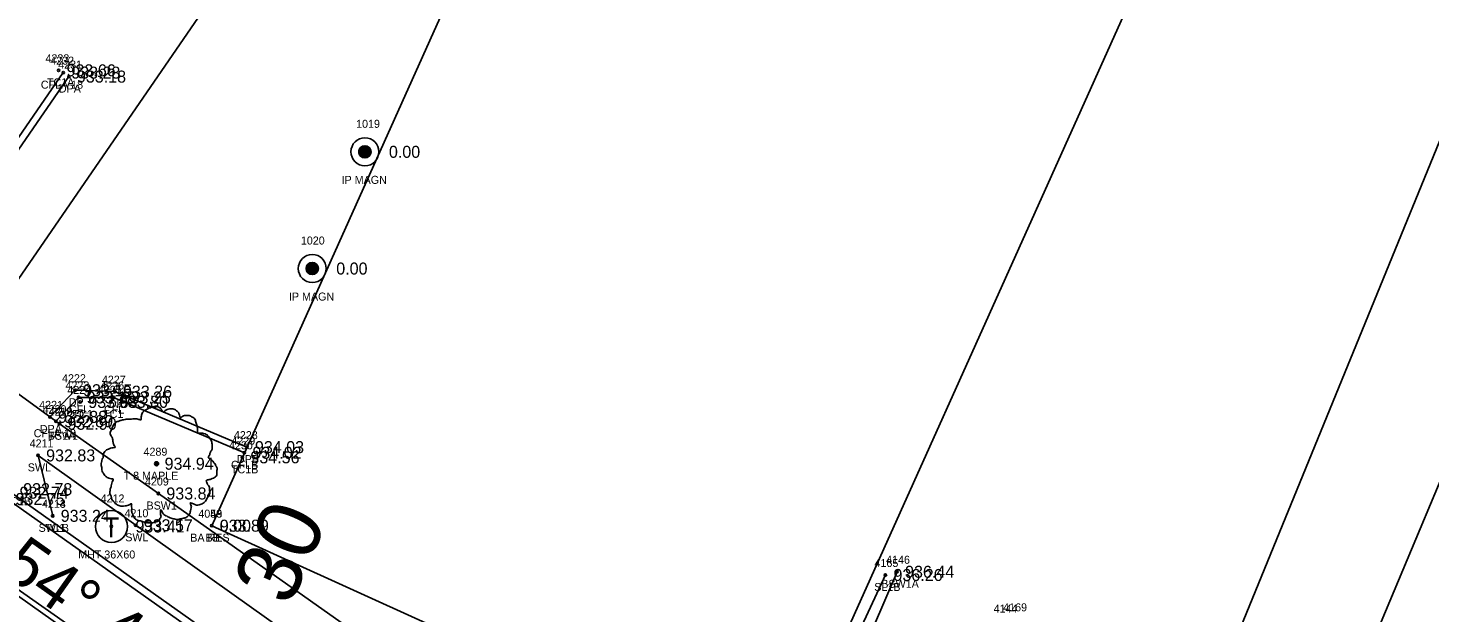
# Model space of a CAD drawing. Extents: x 1575382 to 1578175, y 1099175 to 1101955.
# Drawn here: x 1577218.2 to 1577393.3, y 1101400.1 to 1101473.2 of the extents above; entities that cross this region are included whole.
import ezdxf

# ---------------------------------------------------------------- set-up
doc = ezdxf.new("R2010")
doc.units = 0
for name, color, linetype in [('RD_EX_Bldg', 7, 'Continuous'), ('RD_EX_Bldg_txCode', 7, 'Continuous'), ('RD_EX_Conc', 7, 'Continuous'), ('RD_EX_Conc_txCode', 7, 'Continuous'), ('RD_EX_DR_Pipe', 7, 'Continuous'), ('RD_EX_Driveway', 7, 'Continuous'), ('RD_EX_Driveway_txCode', 7, 'Continuous'), ('RD_EX_DV_Prop_txCode', 7, 'Continuous'), ('RD_EX_DV_PropPin', 7, 'Continuous'), ('RD_EX_Road', 7, 'Continuous'), ('RD_EX_SU_Telecom', 7, 'Continuous'), ('RD_EX_TX_Bldg_ELEV', 7, 'Continuous'), ('RD_EX_TX_Conc_ELEV', 7, 'Continuous'), ('RD_EX_TX_Driveway_ELEV', 7, 'Continuous'), ('RD_EX_TX_DV_Prop_ELEV', 7, 'Continuous'), ('RD_EX_TX_Road_ELEV', 7, 'Continuous'), ('RD_EX_TX_UT_ELEV', 7, 'Continuous'), ('RD_EX_TX_VEG_ELEV', 7, 'Continuous'), ('RD_EX_UT', 7, 'Continuous'), ('RD_EX_UT_txCode', 7, 'Continuous'), ('RD_EX_VEG', 7, 'Continuous'), ('RD_EX_VEG_txCode', 7, 'Continuous'), ('RD_HC_Cl', 7, 'Continuous'), ('RD_HC_Data', 7, 'Continuous'), ('RD_HC_TX_Sta50', 7, 'Continuous'), ('RD_SMD_Locator', 7, 'Continuous')]:
    doc.layers.add(name, color=color, linetype=linetype)

msp = doc.modelspace()

# ---------------------------------------------------------------- linework, layer by layer
at = {"layer": 'RD_EX_Bldg'}
msp.add_lwpolyline([(1577241.11, 1101410.99), (1577311.94, 1101378.81), (1577394.95, 1101563.59), (1577324.12, 1101595.78), (1577241.11, 1101410.99)], dxfattribs=at)
at = {"layer": 'RD_EX_Conc'}
for points in [[(1577326.74, 1101405.23), (1577316.35, 1101381.05), (1577314.7, 1101377.45), (1577312.77, 1101373.03), (1577307.57, 1101368.22), (1577302.65, 1101367.84), (1577295.88, 1101371.65), (1577262.96, 1101394.89), (1577234.44, 1101415.01), (1577222.09, 1101423.72), (1577202.94, 1101437.61), (1577200.92, 1101438.92), (1577194.11, 1101443.95), (1577177.58, 1101455.53), (1577173.58, 1101458.39), (1577156.82, 1101470.2), (1577152.82, 1101472.9), (1577143.37, 1101479.79), (1577139.03, 1101482.93)], [(1577222.56, 1101467.58), (1577206.78, 1101444.68), (1577203.8, 1101441.89)], [(1577221.65, 1101424.04), (1577224.47, 1101427.01), (1577228.85, 1101427), (1577245.2, 1101420.1)], [(1577305.91, 1101358.4), (1577259.94, 1101390.92), (1577231.61, 1101411.04), (1577219.42, 1101419.77), (1577221.24, 1101412.22)], [(1577306.23, 1101358.15), (1577304.05, 1101352.9), (1577257.21, 1101385.98), (1577216.1, 1101415.11)]]:
    msp.add_lwpolyline(points, dxfattribs=at)
at = {"layer": 'RD_EX_DR_Pipe'}
msp.add_lwpolyline([(1577244.79, 1101065.98), (1577363.73, 1101342.96), (1577363.73, 1101342.96), (1577441.43, 1101528.3)], dxfattribs=at)
at = {"layer": 'RD_EX_Driveway'}
for points in [[(1577223.27, 1101467.09), (1577203.54, 1101438.52), (1577202.94, 1101437.61)], [(1577220.9, 1101424.58), (1577224.04, 1101427.91), (1577229.02, 1101427.73), (1577245.51, 1101420.8)]]:
    msp.add_lwpolyline(points, dxfattribs=at)
at = {"layer": 'RD_EX_DV_PropPin'}
for p, q in [((1577259.55, 1101457.4), (1577259.55, 1101457.99)), ((1577259.58, 1101457.33), (1577259.58, 1101458.06)), ((1577259.62, 1101457.27), (1577259.62, 1101458.12)), ((1577259.65, 1101457.22), (1577259.65, 1101458.17)), ((1577259.69, 1101457.18), (1577259.69, 1101458.21)), ((1577259.72, 1101457.14), (1577259.72, 1101458.25)), ((1577259.76, 1101457.11), (1577259.76, 1101458.28)), ((1577259.79, 1101457.08), (1577259.79, 1101458.3)), ((1577259.83, 1101457.06), (1577259.83, 1101458.33)), ((1577259.86, 1101457.04), (1577259.86, 1101458.35)), ((1577259.9, 1101457.02), (1577259.9, 1101458.37)), ((1577259.93, 1101457), (1577259.93, 1101458.39)), ((1577259.97, 1101456.99), (1577259.97, 1101458.4)), ((1577260, 1101456.97), (1577260, 1101458.42)), ((1577260.04, 1101456.96), (1577260.04, 1101458.43)), ((1577260.07, 1101456.95), (1577260.07, 1101458.44)), ((1577260.11, 1101456.95), (1577260.11, 1101458.44)), ((1577260.14, 1101456.94), (1577260.14, 1101458.45)), ((1577260.18, 1101456.94), (1577260.18, 1101458.45)), ((1577260.21, 1101456.93), (1577260.21, 1101458.46)), ((1577260.25, 1101456.93), (1577260.25, 1101458.46)), ((1577260.28, 1101456.93), (1577260.28, 1101458.46)), ((1577260.32, 1101456.94), (1577260.32, 1101458.45)), ((1577260.35, 1101456.94), (1577260.35, 1101458.45)), ((1577260.39, 1101456.95), (1577260.39, 1101458.44)), ((1577260.42, 1101456.95), (1577260.42, 1101458.44)), ((1577260.46, 1101456.96), (1577260.46, 1101458.43)), ((1577260.49, 1101456.97), (1577260.49, 1101458.42)), ((1577260.53, 1101456.99), (1577260.53, 1101458.4)), ((1577260.56, 1101457), (1577260.56, 1101458.39)), ((1577260.6, 1101457.02), (1577260.6, 1101458.37)), ((1577260.63, 1101457.04), (1577260.63, 1101458.35)), ((1577260.67, 1101457.06), (1577260.67, 1101458.33)), ((1577260.7, 1101457.08), (1577260.7, 1101458.3)), ((1577260.74, 1101457.11), (1577260.74, 1101458.28)), ((1577260.77, 1101457.14), (1577260.77, 1101458.25)), ((1577260.81, 1101457.18), (1577260.81, 1101458.21)), ((1577260.85, 1101457.22), (1577260.85, 1101458.17)), ((1577260.88, 1101457.27), (1577260.88, 1101458.12)), ((1577260.92, 1101457.33), (1577260.92, 1101458.06)), ((1577260.95, 1101457.4), (1577260.95, 1101457.99)), ((1577259.51, 1101457.5), (1577259.51, 1101457.89)), ((1577260.99, 1101457.5), (1577260.99, 1101457.89)), ((1577252.94, 1101442.91), (1577252.94, 1101443.31)), ((1577252.97, 1101442.81), (1577252.97, 1101443.41)), ((1577253.01, 1101442.74), (1577253.01, 1101443.48)), ((1577253.04, 1101442.68), (1577253.04, 1101443.54)), ((1577253.08, 1101442.64), (1577253.08, 1101443.58)), ((1577253.11, 1101442.59), (1577253.11, 1101443.62)), ((1577253.15, 1101442.56), (1577253.15, 1101443.66)), ((1577253.18, 1101442.53), (1577253.18, 1101443.69)), ((1577253.22, 1101442.5), (1577253.22, 1101443.72)), ((1577253.25, 1101442.47), (1577253.25, 1101443.74)), ((1577253.29, 1101442.45), (1577253.29, 1101443.77)), ((1577253.32, 1101442.43), (1577253.32, 1101443.79)), ((1577253.36, 1101442.42), (1577253.36, 1101443.8)), ((1577253.39, 1101442.4), (1577253.39, 1101443.82)), ((1577253.43, 1101442.39), (1577253.43, 1101443.83)), ((1577253.46, 1101442.38), (1577253.46, 1101443.84)), ((1577253.5, 1101442.37), (1577253.5, 1101443.85)), ((1577253.53, 1101442.36), (1577253.53, 1101443.86)), ((1577253.57, 1101442.36), (1577253.57, 1101443.86)), ((1577253.6, 1101442.35), (1577253.6, 1101443.87)), ((1577253.64, 1101442.35), (1577253.64, 1101443.87)), ((1577253.67, 1101442.35), (1577253.67, 1101443.87)), ((1577253.71, 1101442.35), (1577253.71, 1101443.87)), ((1577253.74, 1101442.35), (1577253.74, 1101443.87)), ((1577253.78, 1101442.36), (1577253.78, 1101443.86)), ((1577253.81, 1101442.36), (1577253.81, 1101443.86)), ((1577253.85, 1101442.37), (1577253.85, 1101443.85)), ((1577253.88, 1101442.38), (1577253.88, 1101443.84)), ((1577253.92, 1101442.39), (1577253.92, 1101443.83)), ((1577253.95, 1101442.4), (1577253.95, 1101443.82)), ((1577253.99, 1101442.42), (1577253.99, 1101443.8)), ((1577254.02, 1101442.43), (1577254.02, 1101443.79)), ((1577254.06, 1101442.45), (1577254.06, 1101443.77)), ((1577254.09, 1101442.47), (1577254.09, 1101443.74)), ((1577254.13, 1101442.5), (1577254.13, 1101443.72)), ((1577254.16, 1101442.53), (1577254.16, 1101443.69)), ((1577254.2, 1101442.56), (1577254.2, 1101443.66)), ((1577254.23, 1101442.59), (1577254.23, 1101443.62)), ((1577254.27, 1101442.64), (1577254.27, 1101443.58)), ((1577254.3, 1101442.68), (1577254.3, 1101443.54)), ((1577254.34, 1101442.74), (1577254.34, 1101443.48)), ((1577254.37, 1101442.81), (1577254.37, 1101443.41)), ((1577254.41, 1101442.91), (1577254.41, 1101443.31))]:
    msp.add_line(p, q, dxfattribs=at)
for centre, radius in [((1577260.25, 1101457.69), 1.75), ((1577260.25, 1101457.69), 0.761), ((1577253.67, 1101443.11), 1.75), ((1577253.67, 1101443.11), 0.761)]:
    msp.add_circle(centre, radius, dxfattribs=at)
at = {"layer": 'RD_EX_Road'}
msp.add_lwpolyline([(1577350.99, 1101394.65), (1577333.62, 1101354.38), (1577330.31, 1101348.32), (1577323.84, 1101345.4), (1577317.43, 1101344.5), (1577311.61, 1101346.41), (1577303.25, 1101352.4), (1577256.62, 1101385.27), (1577215.6, 1101414.32), (1577175.52, 1101442.94), (1577135.2, 1101471.71)], dxfattribs=at)
at = {"layer": 'RD_EX_SU_Telecom'}
msp.add_circle((1577228.58, 1101410.89), 2, dxfattribs=at)
at = {"layer": 'RD_EX_UT'}
msp.add_line((1577284.56, 1101540.07), (1577198.95, 1101415.64), dxfattribs=at)
for points in [[(1577437.16, 1101563.25), (1577337.02, 1101318.59), (1577272.89, 1101163.98), (1577227.14, 1101061.98), (1577386.9, 1100948.15), (1577403.9, 1100879.99)], [(1577014.29, 1101543.33), (1577198.95, 1101415.64), (1577337.02, 1101318.59)]]:
    msp.add_lwpolyline(points, dxfattribs=at)
at = {"layer": 'RD_EX_VEG'}
msp.add_line((1577315.02, 1101382.74), (1577325.29, 1101404.83), dxfattribs=at)
for centre, radius in [((1577234.22, 1101418.73), 0.25), ((1577234.21, 1101418.71), 0.0001)]:
    msp.add_circle(centre, radius, dxfattribs=at)
for points in [[(1577234.36, 1101425.9), (1577234.06, 1101425.93), (1577233.73, 1101425.83), (1577233.48, 1101425.73), (1577233.26, 1101425.65), (1577233.03, 1101425.55), (1577232.73, 1101425.38), (1577232.51, 1101425.18), (1577232.38, 1101424.93), (1577232.33, 1101424.7), (1577232.28, 1101424.43), (1577232.28, 1101424.25), (1577232.16, 1101424.23), (1577232.01, 1101424.25), (1577231.76, 1101424.33), (1577231.51, 1101424.33), (1577231.26, 1101424.33), (1577230.91, 1101424.3), (1577230.56, 1101424.3), (1577230.28, 1101424.25), (1577229.96, 1101424.2), (1577229.58, 1101424.08), (1577229.23, 1101423.95), (1577228.93, 1101423.7), (1577228.68, 1101423.23), (1577228.56, 1101422.88), (1577228.41, 1101422.63), (1577228.56, 1101422.18), (1577228.73, 1101421.83), (1577228.76, 1101421.63), (1577228.83, 1101421.2), (1577228.93, 1101420.98), (1577229.06, 1101420.78), (1577228.98, 1101420.75), (1577228.61, 1101420.7), (1577228.31, 1101420.6), (1577227.88, 1101420.38), (1577227.66, 1101420.15), (1577227.56, 1101419.83), (1577227.53, 1101419.48), (1577227.43, 1101419.28), (1577227.36, 1101419), (1577227.33, 1101418.93), (1577227.28, 1101418.6), (1577227.38, 1101418.15), (1577227.41, 1101417.8), (1577227.53, 1101417.58), (1577227.68, 1101417.4), (1577227.86, 1101417.15), (1577228.26, 1101416.93), (1577228.58, 1101416.83), (1577228.78, 1101416.8), (1577228.61, 1101416.31), (1577228.56, 1101415.96), (1577228.43, 1101415.56), (1577228.43, 1101415.48), (1577228.38, 1101415.01), (1577228.53, 1101414.68), (1577228.61, 1101414.31), (1577228.78, 1101414.08), (1577229.06, 1101413.78), (1577229.38, 1101413.56), (1577229.88, 1101413.43), (1577230.28, 1101413.46), (1577230.86, 1101413.63), (1577231.11, 1101413.71), (1577231.08, 1101413.53), (1577231.11, 1101413.16), (1577231.11, 1101412.73), (1577231.26, 1101412.41), (1577231.36, 1101412.13), (1577231.51, 1101411.88), (1577231.83, 1101411.66), (1577232.23, 1101411.58), (1577232.66, 1101411.43), (1577233.11, 1101411.36), (1577233.61, 1101411.33), (1577234.21, 1101411.48), (1577234.48, 1101411.61), (1577234.58, 1101411.78), (1577234.78, 1101412.16), (1577234.73, 1101412.38), (1577234.76, 1101412.98), (1577234.86, 1101412.81), (1577235.03, 1101412.46), (1577235.53, 1101412.16), (1577235.93, 1101411.98), (1577236.4, 1101411.83), (1577236.7, 1101411.76), (1577237.18, 1101411.83), (1577237.55, 1101411.91), (1577237.93, 1101412.03), (1577238.23, 1101412.31), (1577238.4, 1101412.58), (1577238.45, 1101412.86), (1577238.53, 1101413.23), (1577238.58, 1101413.41)], [(1577238.58, 1101413.41), (1577238.5, 1101413.58), (1577238.45, 1101413.83), (1577238.53, 1101413.81), (1577238.7, 1101413.76), (1577238.98, 1101413.63), (1577239.2, 1101413.56), (1577239.53, 1101413.58), (1577239.8, 1101413.68), (1577240.25, 1101413.96), (1577240.53, 1101414.43), (1577240.8, 1101414.83), (1577240.88, 1101415.16), (1577240.83, 1101415.38), (1577240.8, 1101415.88), (1577240.6, 1101416.13), (1577240.55, 1101416.26), (1577240.45, 1101416.65), (1577240.53, 1101416.7), (1577240.8, 1101416.75), (1577241.18, 1101416.88), (1577241.45, 1101417), (1577241.68, 1101417.18), (1577241.75, 1101417.4), (1577241.73, 1101417.8), (1577241.78, 1101418.2), (1577241.7, 1101418.35), (1577241.6, 1101418.5), (1577241.53, 1101418.7), (1577241.38, 1101418.85), (1577241.28, 1101419), (1577241.18, 1101419.1), (1577241.05, 1101419.25), (1577240.88, 1101419.38), (1577240.73, 1101419.43), (1577240.68, 1101419.58), (1577240.83, 1101419.78), (1577240.88, 1101419.88), (1577240.9, 1101420.1), (1577241.13, 1101420.45), (1577241.18, 1101420.85), (1577241.13, 1101421.28), (1577241.08, 1101421.55), (1577240.93, 1101421.83), (1577240.73, 1101422.08), (1577240.6, 1101422.25), (1577240.43, 1101422.38), (1577240.1, 1101422.5), (1577239.85, 1101422.55), (1577239.5, 1101422.55), (1577239.3, 1101422.6), (1577239.33, 1101422.65), (1577239.33, 1101422.8), (1577239.33, 1101423.08), (1577239.25, 1101423.53), (1577239.1, 1101424.03), (1577239.1, 1101424.05), (1577239, 1101424.3), (1577238.78, 1101424.5), (1577238.6, 1101424.6), (1577238.4, 1101424.73), (1577238.15, 1101424.75), (1577237.85, 1101424.75), (1577237.58, 1101424.7), (1577237.38, 1101424.6), (1577237.2, 1101424.48), (1577237.13, 1101424.63), (1577237.03, 1101424.93), (1577236.98, 1101425.08), (1577236.83, 1101425.25), (1577236.6, 1101425.45), (1577236.15, 1101425.58), (1577235.53, 1101425.5), (1577235.23, 1101425.3), (1577235.08, 1101425.13), (1577235.03, 1101425.25), (1577234.83, 1101425.45), (1577234.73, 1101425.63), (1577234.56, 1101425.75), (1577234.41, 1101425.85), (1577234.31, 1101425.9)]]:
    msp.add_spline(points, degree=3, dxfattribs=at)
at = {"layer": 'RD_HC_Cl'}
msp.add_line((1577333.44, 1101319.83), (1577129.25, 1101464.19), dxfattribs=at)
at = {"layer": 'RD_SMD_Locator'}
for centre in [(1577221.97, 1101467.87), (1577222.56, 1101467.58), (1577223.27, 1101467.09), (1577260.25, 1101457.69), (1577253.67, 1101443.11), (1577224.04, 1101427.91), (1577224.47, 1101427.01), (1577224.69, 1101426.44), (1577228.51, 1101426.46), (1577228.85, 1101427), (1577229.02, 1101427.73), (1577220.9, 1101424.58), (1577221.65, 1101424.04), (1577222.09, 1101423.72), (1577222.09, 1101423.72), (1577219.42, 1101419.77), (1577244.94, 1101419.53), (1577245.2, 1101420.1), (1577245.51, 1101420.8), (1577234.22, 1101418.73), (1577234.44, 1101415.01), (1577221.24, 1101412.22), (1577221.24, 1101412.22), (1577228.58, 1101410.89), (1577231.61, 1101411.04), (1577241.11, 1101410.99), (1577241.11, 1101410.99), (1577325.29, 1101404.83), (1577326.74, 1101405.23)]:
    msp.add_circle(centre, 0.15, dxfattribs=at)

# ---------------------------------------------------------------- texts
at = {"layer": 'RD_EX_Bldg_txCode'}
for s, p in [('4049', (1577239.44, 1101411.99)), ('4053', (1577239.44, 1101411.99)), ('BA RES', (1577238.43, 1101408.99)), ('BB', (1577240.33, 1101408.99))]:
    msp.add_text(s, height=1, dxfattribs=at).set_placement(p)
at = {"layer": 'RD_EX_Conc_txCode'}
for s, p in [('4233', (1577220.34, 1101468.87)), ('4232', (1577220.93, 1101468.58)), ('TC1A', (1577220.52, 1101465.87)), ('CFLA 18', (1577219.76, 1101465.58)), ('4223', (1577222.84, 1101428.01)), ('4224', (1577223.06, 1101427.44)), ('4225', (1577226.88, 1101427.46)), ('4226', (1577227.2, 1101428)), ('4220', (1577219.98, 1101425.04)), ('4218', (1577220.74, 1101424.72)), ('4219', (1577220.74, 1101424.72)), ('CFL', (1577223.27, 1101425.01)), ('TC1', (1577223.73, 1101424.44)), ('TC1', (1577227.55, 1101424.46)), ('CFL', (1577227.65, 1101425)), ('CFLA 18', (1577218.86, 1101422.04)), ('4211', (1577218.36, 1101420.77)), ('TC1A', (1577220.64, 1101421.72)), ('BSW1', (1577220.61, 1101421.72)), ('4230', (1577243.27, 1101420.53)), ('4229', (1577243.57, 1101421.1)), ('SWL', (1577218.13, 1101417.77)), ('TC1B', (1577243.51, 1101417.53)), ('CFLB', (1577243.52, 1101418.1)), ('4209', (1577232.77, 1101416.01)), ('TC1B', (1577215.12, 1101413.55)), ('4213', (1577219.9, 1101413.22)), ('4214', (1577219.9, 1101413.22)), ('4210', (1577230.22, 1101412.04)), ('BSW1', (1577232.96, 1101413.01)), ('SWLB', (1577219.48, 1101410.22)), ('TC1', (1577220.28, 1101410.22)), ('SWL', (1577230.31, 1101409.04)), ('4146', (1577325.37, 1101406.23)), ('BSW1A', (1577324.77, 1101403.23)), ('4144', (1577338.8, 1101400.12))]:
    msp.add_text(s, height=1, dxfattribs=at).set_placement(p)
at = {"layer": 'RD_EX_Driveway_txCode'}
for s, p in [('4231', (1577221.93, 1101468.09)), ('DPA', (1577222.01, 1101465.09)), ('4222', (1577222.41, 1101428.91)), ('4227', (1577227.39, 1101428.73)), ('4221', (1577219.55, 1101425.58)), ('DP', (1577223.26, 1101425.91)), ('DP', (1577228.25, 1101425.73)), ('DPA', (1577219.63, 1101422.58)), ('4228', (1577243.88, 1101421.8)), ('DPB', (1577244.26, 1101418.8))]:
    msp.add_text(s, height=1, dxfattribs=at).set_placement(p)
at = {"layer": 'RD_EX_DV_Prop_txCode'}
for s, p in [('1019', (1577259.15, 1101460.69)), ('IP MAGN', (1577257.34, 1101453.69)), ('1020', (1577252.25, 1101446.11)), ('IP MAGN', (1577250.76, 1101439.11))]:
    msp.add_text(s, height=1, dxfattribs=at).set_placement(p)
at = {"layer": 'RD_EX_SU_Telecom'}
msp.add_text('T', height=2.5, dxfattribs=at).set_placement((1577227.52, 1101409.52))
at = {"layer": 'RD_EX_TX_Bldg_ELEV'}
for s in ['0.00', '933.89']:
    msp.add_text(s, height=1.5, dxfattribs=at).set_placement((1577242.11, 1101410.24))
at = {"layer": 'RD_EX_TX_Conc_ELEV'}
for s, p in [('933.66', (1577222.97, 1101467.12)), ('933.23', (1577223.56, 1101466.83)), ('933.15', (1577225.47, 1101426.26)), ('933.68', (1577225.69, 1101425.69)), ('933.80', (1577229.51, 1101425.71)), ('933.25', (1577229.85, 1101426.25)), ('932.89', (1577222.65, 1101423.29)), ('932.90', (1577223.09, 1101422.97)), ('932.90', (1577223.09, 1101422.97)), ('932.83', (1577220.42, 1101419.02)), ('934.56', (1577245.94, 1101418.78)), ('934.02', (1577246.2, 1101419.35)), ('932.78', (1577217.55, 1101414.8)), ('932.74', (1577217.1, 1101414.36)), ('933.84', (1577235.44, 1101414.26)), ('933.24', (1577222.24, 1101411.47)), ('933.24', (1577222.24, 1101411.47)), ('933.57', (1577232.61, 1101410.29)), ('936.44', (1577327.74, 1101404.48))]:
    msp.add_text(s, height=1.5, dxfattribs=at).set_placement(p)
at = {"layer": 'RD_EX_TX_Driveway_ELEV'}
for s, p in [('933.18', (1577224.27, 1101466.34)), ('933.15', (1577225.04, 1101427.16)), ('933.26', (1577230.02, 1101426.98)), ('932.88', (1577221.9, 1101423.83)), ('934.03', (1577246.51, 1101420.05))]:
    msp.add_text(s, height=1.5, dxfattribs=at).set_placement(p)
at = {"layer": 'RD_EX_TX_DV_Prop_ELEV'}
for p in [(1577263.25, 1101456.94), (1577256.67, 1101442.36)]:
    msp.add_text('0.00', height=1.5, dxfattribs=at).set_placement(p)
at = {"layer": 'RD_EX_TX_Road_ELEV'}
msp.add_text('932.75', height=1.5, dxfattribs=at).set_placement((1577216.6, 1101413.57))
at = {"layer": 'RD_EX_TX_UT_ELEV'}
msp.add_text('933.41', height=1.5, dxfattribs=at).set_placement((1577231.58, 1101410.14))
at = {"layer": 'RD_EX_TX_VEG_ELEV'}
for s, p in [('934.94', (1577235.22, 1101417.98)), ('936.26', (1577326.29, 1101404.08))]:
    msp.add_text(s, height=1.5, dxfattribs=at).set_placement(p)
at = {"layer": 'RD_EX_UT_txCode'}
for s, p in [('4212', (1577227.23, 1101413.89)), ('MHT 36X60', (1577224.42, 1101406.89))]:
    msp.add_text(s, height=1, dxfattribs=at).set_placement(p)
at = {"layer": 'RD_EX_VEG_txCode'}
for s, p in [('4289', (1577232.59, 1101419.73)), ('T 8 MAPLE', (1577230.1, 1101416.73)), ('4165', (1577323.92, 1101405.83)), ('SL1B', (1577323.89, 1101402.83)), ('4169', (1577340, 1101400.29))]:
    msp.add_text(s, height=1, dxfattribs=at).set_placement(p)
at = {"layer": 'RD_HC_Data'}
msp.add_text('N 54%%d 44\' 26" W', height=6, rotation=324.7406, dxfattribs=at).set_placement((1577207.98, 1101409.75))
at = {"layer": 'RD_HC_TX_Sta50'}
msp.add_text('30', height=8, rotation=66.4777, dxfattribs=at).set_placement((1577250.86, 1101400.72))

doc.saveas('drawing.dxf')
